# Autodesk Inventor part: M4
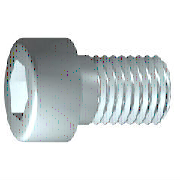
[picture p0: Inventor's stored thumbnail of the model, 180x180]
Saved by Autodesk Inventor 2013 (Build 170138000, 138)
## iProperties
IsCustomPart: 0
Created: 2014-10
Part Number: M4
Material: 강철, 연강
Description: 6각머리 태핑 나사
Document SubType Name: Modeling
Standard: KS B 1003
Designer: KYOUNG IL JANG
Standards Organization: KS
Language: ko-KR
Size Designation: M 4 x 10
Categories: <MemberInstance><Categories><Category DisplayName="조임쇠" InternalName="e4da775c-781d-43d5-af7c-5136215cf5a6" Mnemonic="FSTN"><Category DisplayName="볼트" InternalN
Density: 7.86 g/cm^3
Mass: 2.0371 g
Surface Area: 3.0572 cm^2
Volume: 0.259174 cm^3
Author: SeoGD™ [www.esajin.kr]
Revision Number: 1
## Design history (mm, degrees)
sketch "스케치1"
  geometry: L1 (-1, 0)-(10, 0); L2 (10, 0)-(10, 2); L3 (10, 2)-(1.75, 2); L4 (1.75, 2)-(1.32, 2); L5 (1.32, 2)-(0, 2); L6 (0, 2)-(0, 3.5); L7 (0, 3.5)-(-4, 3.5); L8 (-4, 3.5)-(-4, 1.732); L9 (-4, 1.732)-(-2, 1.732); L10 (-2, 1.732)-(-1, 0); L11 (-6.8, 0)-(12.8, 0) reference; L12 (0, -0.7)-(0, 4.2) reference; L13 (1.75, 2)-(0, 2)
  constraints: 22 end point, 6 parallel, 2 collinear, 2 perpendicular, 1 horizontal, 1 point on line
  dimensions: "d1" = 8.25 distance from line of L3.end L2 (= GEL); "d2" = 0.42952 distance of L4.end L3.end (computed from GAL); "d3" = 4 distance between parallel lines of L8 L6 (= KOH); "d4" = 2 distance of L8.end L9.end (= INTI); "d5" = 60 deg angle of L10 L1; "d6" = 4 diameter of L3 L1 (= GD); "d7" = 4 diameter of L5 L1 (= BDM); "d8" = 3.4641 diameter of L9 L1 (= 1.1547 x SW); "d9" = 7 diameter of L7 L1 (= KOD); "d26" = 10 distance between parallel lines of L12 L2 (= NLG)
revolve "본체" sketch "스케치1" stored, may be unused: angle "d10" = 90 deg
sketch "스케치2"
  geometry: L1 (0, -4.9)-(0, 4.9) reference; L2 (-4.9, 0)-(4.9, 0) reference; L3 (1.732, 0)-(0.866, -1.5); L4 (0.866, -1.5)-(-0.866, -1.5); L5 (-0.866, -1.5)-(-1.732, 0); L6 (-1.732, 0)-(-0.866, 1.5); L7 (-0.866, 1.5)-(0.866, 1.5); L8 (0.866, 1.5)-(1.732, 0); 2 further points
  constraints: 12 end point, 1 coincident, 1 horizontal alignment, 1 point on line, 12 other
extrude "슬롯" join sketch "스케치2" stored distance "d11" = 10; taper "d12" = 0 deg
workplane "Work Plane1"
fillet "Fillet2" dims "d30" = 0.1 (= R)
body "Solid1"
fillet "모깎기1" dims "d17" = 0.4 (= RR)
feature "스레드" dims "d13" = 8.25 (= GEL), "d14" = 0
chamfer "모따기1" distance "d15" = 0.42941 (= -0.5 x SPD + 0.5 x GD); stored, may be unused: second distance "d16" = 0.42941 (= GUL), angle "d27" = 45 deg
other parameters: "GD" = 4 (= NND) [user parameter; used in 2 equation terms], "NLG" = 10 [user parameter; used in 1 equation term], "GEL" = 8.25 [user parameter; used in 2 equation terms], "KOD" = 7 [user parameter; used in 1 equation term], "KOH" = 4 [user parameter; used in 1 equation term], "INTI" = 2 [user parameter; used in 1 equation term], "GAL" = 0.42941 (= 0.61345 x PTC) [user parameter; used in 1 equation term], "GUL" = 0.42941 (= 0.61345 x PTC) [user parameter; used in 1 equation term], "BDM" = 4 (= NND) [user parameter; used in 1 equation term], "SW" = 3 [user parameter; used in 2 equation terms], "RR" = 0.4 [user parameter; used in 1 equation term], "SPD" = 3.14117 (= NND - 1.2269 x PTC) [user parameter; used in 1 equation term], "d19" = 0, "d28" = 0, "d29" = 0, "R" = 0.1 [user parameter; used in 1 equation term], "PHH" = 0.2 [user parameter], "GD1" = 3.14117 (= THREADDIA - 1.2269 x PTC) [user parameter], "THREADDIA" = 4 [user parameter; used in 1 equation term], "FAWI" = 45 deg [user parameter], "TPU" = 14.28571 (computed from PTC) [user parameter], "PTC" = 0.7 [user parameter; used in 5 equation terms], "NND" = 4 [user parameter; used in 3 equation terms], "TOA" = 30 deg [user parameter], "E0" = 3.465 (= 1.155 x SW) [user parameter]
